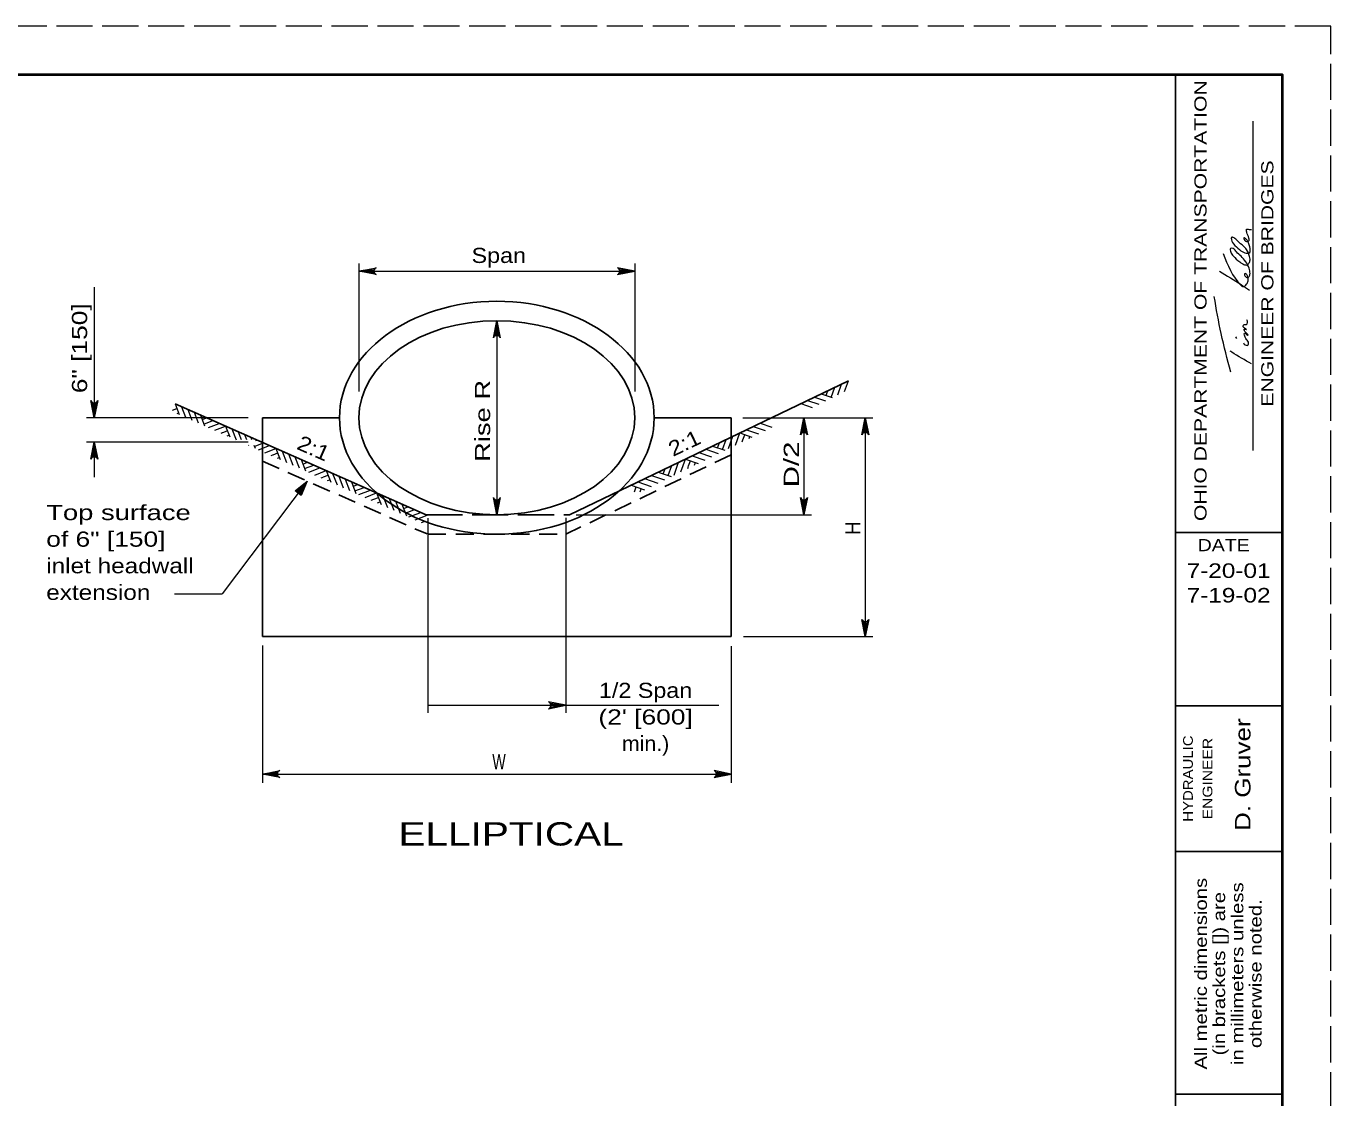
# Model space of a CAD drawing. Extents: x 685.4 to 719.4, y 1059.8 to 1105.8.
# Drawn here: x 706.01 to 719.44, y 1094.73 to 1105.77 of the extents above; entities that cross this region are included whole.
import ezdxf
from ezdxf.enums import TextEntityAlignment as Align

# ---------------------------------------------------------------- set-up
doc = ezdxf.new("R2010")
doc.units = 0
doc.header["$LTSCALE"] = 0.062
doc.linetypes.add('LONG_DASHED', pattern=[7.5, 6, -1.5])
doc.linetypes.add('MEDIUM_DASHED', pattern=[4.5, 3, -1.5])
doc.layers.add('1', color=7, linetype='Continuous', lineweight=13)

msp = doc.modelspace()

# ---------------------------------------------------------------- hatches: boundary and pattern name
at = {"layer": '1'}
msp.add_hatch(color=256, dxfattribs=at).paths.add_polyline_path([(708.78058, 1100.9845), (708.90567, 1101.08558), (708.84283, 1100.93758)])

# ---------------------------------------------------------------- linework, layer by layer
at = {"layer": '1', "lineweight": 25}
for p, q in [((687.44108, 1105.27067), (718.94108, 1105.27067)), ((717.84108, 1084.27067), (717.84108, 1105.27067)), ((718.94108, 1105.27067), (718.94108, 1084.27067)), ((714.47483, 1102.11825), (711.60375, 1100.738)), ((707.54717, 1101.88017), (710.13042, 1100.738)), ((708.4455, 1099.48433), (708.4455, 1101.73742)), ((708.4455, 1101.73742), (709.23825, 1101.73742)), ((712.47667, 1101.73742), (713.26933, 1101.73742)), ((713.26933, 1099.48433), (713.26933, 1101.73742)), ((718.94108, 1100.55483), (717.84108, 1100.55483)), ((708.4455, 1099.48433), (713.26933, 1099.48433)), ((718.94108, 1098.77067), (717.84108, 1098.77067)), ((718.94108, 1097.27067), (717.84108, 1097.27067)), ((718.94108, 1094.77067), (717.84108, 1094.77067))]:
    msp.add_line(p, q, dxfattribs=at)
at = {"layer": '1'}
for p, q in [((718.63983, 1101.40167), (718.63983, 1104.79175)), ((709.43817, 1103.32583), (709.43817, 1102.00808)), ((712.27683, 1103.32583), (712.27683, 1102.00808)), ((709.59842, 1103.26958), (709.43817, 1103.24717)), ((709.59292, 1103.2585), (709.43817, 1103.24717)), ((709.43817, 1103.24717), (712.27683, 1103.24717)), ((709.59133, 1103.24717), (709.43817, 1103.24717)), ((709.59417, 1103.23283), (709.43817, 1103.24717)), ((709.60025, 1103.22242), (709.43817, 1103.24717)), ((712.11467, 1103.22242), (712.27683, 1103.24717)), ((712.11658, 1103.26958), (712.27683, 1103.24717)), ((712.12083, 1103.23283), (712.27683, 1103.24717)), ((712.122, 1103.2585), (712.27683, 1103.24717)), ((712.12367, 1103.24717), (712.27683, 1103.24717)), ((706.71392, 1103.08342), (706.71392, 1101.73742)), ((710.83267, 1102.57467), (710.85742, 1102.73683)), ((710.84308, 1102.58083), (710.85742, 1102.73683)), ((710.85742, 1102.58367), (710.85742, 1102.73683)), ((710.86875, 1102.582), (710.85742, 1102.73683)), ((710.87983, 1102.57658), (710.85742, 1102.73683)), ((718.47233, 1102.55258), (718.46217, 1102.57183)), ((714.36567, 1101.97233), (714.40508, 1102.08467)), ((714.43575, 1102.00675), (714.47483, 1102.11825)), ((714.1255, 1101.95033), (714.2395, 1101.91042)), ((714.19542, 1101.98392), (714.30842, 1101.94425)), ((714.247, 1101.96575), (714.26517, 1102.0175)), ((714.29883, 1101.94758), (714.33517, 1102.05117)), ((706.6915, 1101.89767), (706.71392, 1101.73742)), ((706.70267, 1101.89225), (706.71392, 1101.73742)), ((706.73875, 1101.8995), (706.71392, 1101.73742)), ((706.72833, 1101.89342), (706.71392, 1101.73742)), ((706.71392, 1101.89058), (706.71392, 1101.73742)), ((707.5185, 1101.81542), (707.56525, 1101.83342)), ((707.54717, 1101.88017), (707.58917, 1101.77158)), ((707.61192, 1101.8515), (707.65408, 1101.74258)), ((707.67675, 1101.82292), (707.719, 1101.71358)), ((713.98567, 1101.88308), (714.10125, 1101.84258)), ((714.05558, 1101.91667), (714.17025, 1101.87642)), ((708.297, 1101.73742), (706.63525, 1101.73742)), ((707.56833, 1101.78083), (707.58333, 1101.78667)), ((707.74158, 1101.79417), (707.78408, 1101.6845)), ((707.80633, 1101.76558), (707.84892, 1101.6555)), ((707.82442, 1101.71892), (707.87108, 1101.73692)), ((707.8425, 1101.67208), (707.936, 1101.70825)), ((707.89042, 1101.63692), (708.00075, 1101.67958)), ((713.3895, 1101.73742), (714.72767, 1101.73742)), ((713.5665, 1101.68158), (713.68717, 1101.63925)), ((713.99258, 1101.57525), (714.01742, 1101.73742)), ((714.003, 1101.58142), (714.01742, 1101.73742)), ((714.01742, 1101.58425), (714.01742, 1101.73742)), ((714.02875, 1101.58258), (714.01742, 1101.73742)), ((714.03983, 1101.57717), (714.01742, 1101.73742)), ((714.62425, 1101.57525), (714.649, 1101.73742)), ((714.63458, 1101.58142), (714.649, 1101.73742)), ((714.649, 1101.58425), (714.649, 1101.73742)), ((714.66033, 1101.58258), (714.649, 1101.73742)), ((714.67142, 1101.57717), (714.649, 1101.73742)), ((707.95475, 1101.60817), (708.0655, 1101.65092)), ((708.01925, 1101.57942), (708.035, 1101.5855)), ((708.03692, 1101.58625), (708.0835, 1101.60433)), ((708.0655, 1101.65092), (708.10867, 1101.53933)), ((708.08367, 1101.55058), (708.10167, 1101.5575)), ((708.13025, 1101.62242), (708.17358, 1101.51033)), ((708.195, 1101.59375), (708.22633, 1101.51275)), ((708.25992, 1101.565), (708.28008, 1101.51275)), ((708.32467, 1101.53642), (708.33383, 1101.51275)), ((713.24283, 1101.42125), (713.28708, 1101.54717)), ((713.313, 1101.45575), (713.35683, 1101.58083)), ((713.35683, 1101.58083), (713.48, 1101.53767)), ((713.39042, 1101.51092), (713.40858, 1101.56267)), ((713.42667, 1101.61442), (713.54892, 1101.5715)), ((713.45342, 1101.52458), (713.46042, 1101.5445)), ((713.49658, 1101.64792), (713.618, 1101.60542)), ((708.297, 1101.4875), (706.63525, 1101.4875)), ((706.68917, 1101.32542), (706.71392, 1101.4875)), ((706.69958, 1101.33158), (706.71392, 1101.4875)), ((706.71392, 1101.4875), (706.71392, 1101.12642)), ((706.71392, 1101.33442), (706.71392, 1101.4875)), ((706.72525, 1101.33275), (706.71392, 1101.4875)), ((706.73633, 1101.32733), (706.71392, 1101.4875)), ((708.30242, 1101.45517), (708.3035, 1101.45233)), ((708.35608, 1101.45517), (708.3685, 1101.42333)), ((708.36083, 1101.44292), (708.45425, 1101.47908)), ((708.37475, 1101.50208), (708.38942, 1101.50775)), ((708.40567, 1101.40667), (708.51908, 1101.4505)), ((708.47008, 1101.37783), (708.58375, 1101.42183)), ((708.58375, 1101.42183), (708.62808, 1101.30725)), ((713.0075, 1101.41283), (713.13483, 1101.36817)), ((713.07742, 1101.44642), (713.20375, 1101.40208)), ((713.12908, 1101.42825), (713.14725, 1101.48)), ((713.18083, 1101.41008), (713.21717, 1101.51358)), ((713.38308, 1101.49008), (713.38967, 1101.50883)), ((708.5345, 1101.349), (708.55333, 1101.35633)), ((708.55517, 1101.357), (708.60183, 1101.37508)), ((708.599, 1101.32025), (708.61992, 1101.32833)), ((708.64858, 1101.39317), (708.69308, 1101.27817)), ((708.71333, 1101.3645), (708.75783, 1101.24917)), ((708.77817, 1101.33592), (708.823, 1101.22008)), ((708.84292, 1101.30725), (708.88783, 1101.19108)), ((708.861, 1101.2605), (708.90775, 1101.27858)), ((712.6815, 1101.14575), (712.72808, 1101.2785)), ((712.75167, 1101.18025), (712.79792, 1101.31208)), ((712.79792, 1101.31208), (712.92767, 1101.26658)), ((712.83142, 1101.24217), (712.84958, 1101.29392)), ((712.86767, 1101.34558), (712.99667, 1101.30042)), ((712.89208, 1101.24908), (712.90142, 1101.27575)), ((712.93758, 1101.37917), (713.06567, 1101.33433)), ((708.87917, 1101.21375), (708.97258, 1101.24992)), ((708.92108, 1101.17633), (709.03733, 1101.22125)), ((708.98542, 1101.1475), (709.10217, 1101.19267)), ((709.0735, 1101.12792), (709.12017, 1101.146)), ((709.10217, 1101.19267), (709.14758, 1101.075)), ((709.16683, 1101.164), (709.2125, 1101.04608)), ((709.23167, 1101.13542), (709.2775, 1101.017)), ((712.44858, 1101.14408), (712.5825, 1101.09708)), ((712.51842, 1101.17767), (712.65142, 1101.131)), ((712.57008, 1101.15958), (712.58825, 1101.21117)), ((712.62192, 1101.14142), (712.65817, 1101.24492)), ((712.82175, 1101.21458), (712.83067, 1101.24008)), ((708.90567, 1101.08558), (708.0305, 1099.92525)), ((709.04983, 1101.11875), (709.07167, 1101.12717)), ((709.11425, 1101.08992), (709.13825, 1101.09917)), ((709.2965, 1101.10667), (709.34242, 1100.988)), ((709.36125, 1101.078), (709.40733, 1100.95892)), ((709.37933, 1101.03142), (709.426, 1101.0495)), ((709.39742, 1100.98458), (709.49092, 1101.02075)), ((712.23892, 1101.04333), (712.37533, 1100.9955)), ((712.2725, 1100.9735), (712.29067, 1101.02517)), ((712.30867, 1101.07683), (712.44433, 1101.02933)), ((712.33067, 1100.97358), (712.34242, 1101.007)), ((712.37858, 1101.11042), (712.51333, 1101.06317)), ((709.43642, 1100.94592), (709.55567, 1100.99208)), ((709.50075, 1100.91717), (709.62042, 1100.9635)), ((709.56508, 1100.8885), (709.58992, 1100.89808)), ((709.59183, 1100.89875), (709.63842, 1100.91675)), ((709.62042, 1100.9635), (709.66708, 1100.84283)), ((709.62975, 1100.85958), (709.65658, 1100.87)), ((709.68517, 1100.93483), (709.732, 1100.81383)), ((709.74992, 1100.90625), (709.79692, 1100.78483)), ((709.81475, 1100.87758), (709.86192, 1100.75583)), ((710.835, 1100.89825), (710.85742, 1100.738)), ((710.84608, 1100.89275), (710.85742, 1100.738)), ((710.88225, 1100.90008), (710.85742, 1100.738)), ((710.87183, 1100.894), (710.85742, 1100.738)), ((710.85742, 1100.89117), (710.85742, 1100.738)), ((713.995, 1100.89825), (714.01742, 1100.738)), ((714.00608, 1100.89275), (714.01742, 1100.738)), ((714.04217, 1100.90008), (714.01742, 1100.738)), ((714.03175, 1100.894), (714.01742, 1100.738)), ((714.01742, 1100.89117), (714.01742, 1100.738)), ((709.87958, 1100.84892), (709.92683, 1100.72683)), ((709.89767, 1100.80217), (709.94433, 1100.82025)), ((709.91575, 1100.75542), (710.00917, 1100.7915)), ((709.95175, 1100.71567), (710.074, 1100.76292)), ((710.01608, 1100.68683), (710.13875, 1100.73433)), ((711.67375, 1100.738), (714.09608, 1100.738)), ((710.08042, 1100.65808), (710.10825, 1100.66883)), ((710.14783, 1100.70342), (710.14783, 1098.69767)), ((711.56717, 1100.708), (711.56717, 1098.69767)), ((707.54008, 1099.92525), (708.0305, 1099.92525)), ((714.62658, 1099.64458), (714.649, 1099.48433)), ((714.63767, 1099.63917), (714.649, 1099.48433)), ((714.67383, 1099.6465), (714.649, 1099.48433)), ((714.66342, 1099.64033), (714.649, 1099.48433)), ((714.649, 1099.6375), (714.649, 1099.48433)), ((708.4455, 1099.392), (708.4455, 1097.97833)), ((713.26933, 1099.38642), (713.26933, 1097.97833)), ((713.39508, 1099.48433), (714.72767, 1099.48433)), ((710.14783, 1098.77633), (713.14267, 1098.77633)), ((711.405, 1098.75158), (711.56717, 1098.77633)), ((711.40692, 1098.79875), (711.56717, 1098.77633)), ((711.41117, 1098.762), (711.56717, 1098.77633)), ((711.41233, 1098.78767), (711.56717, 1098.77633)), ((711.414, 1098.77633), (711.56717, 1098.77633)), ((708.60575, 1098.09075), (708.4455, 1098.06833)), ((708.60033, 1098.07967), (708.4455, 1098.06833)), ((708.59867, 1098.06833), (708.4455, 1098.06833)), ((708.6015, 1098.054), (708.4455, 1098.06833)), ((708.60767, 1098.04358), (708.4455, 1098.06833)), ((708.4455, 1098.06833), (713.26933, 1098.06833)), ((713.10717, 1098.04358), (713.26933, 1098.06833)), ((713.10908, 1098.09075), (713.26933, 1098.06833)), ((713.11333, 1098.054), (713.26933, 1098.06833)), ((713.1145, 1098.07967), (713.26933, 1098.06833)), ((713.11617, 1098.06833), (713.26933, 1098.06833))]:
    msp.add_line(p, q, dxfattribs=at)
at = {"layer": '1', "linetype": 'MEDIUM_DASHED', "lineweight": 25}
for p, q in [((708.4455, 1101.28908), (710.13875, 1100.54042)), ((713.26933, 1101.35633), (711.56725, 1100.53808)), ((710.14783, 1100.53808), (711.56725, 1100.53808))]:
    msp.add_line(p, q, dxfattribs=at)
at = {"layer": '1', "linetype": 'LONG_DASHED', "lineweight": 25}
msp.add_line((710.13042, 1100.738), (711.60375, 1100.738), dxfattribs=at)
at = {"layer": '1', "linetype": 'LONG_DASHED'}
msp.add_lwpolyline([(685.44108, 1083.77067), (719.44108, 1083.77067), (719.44108, 1105.77067), (685.44108, 1105.77067)], close=True, dxfattribs=at)
at = {"layer": '1', "lineweight": 40}
msp.add_lwpolyline([(687.44108, 1105.27067), (718.94108, 1105.27067), (718.94108, 1084.27067), (687.44108, 1084.27067)], close=True, dxfattribs=at)
at = {"layer": '1'}
for points in [[(709.61517, 1103.21183), (709.43817, 1103.24717), (709.61517, 1103.28258)], [(712.09983, 1103.21183), (712.27683, 1103.24717), (712.09983, 1103.28258)], [(710.822, 1102.55983), (710.85742, 1102.73683), (710.89283, 1102.55983)], [(710.8575, 1102.73683), (710.8575, 1101.61675), (710.8575, 1100.738)], [(706.74933, 1101.91442), (706.71392, 1101.73742), (706.67858, 1101.91442)], [(713.982, 1101.56042), (714.01742, 1101.73742), (714.05283, 1101.56042)], [(714.01742, 1101.73742), (714.01742, 1101.111), (714.01742, 1100.738)], [(714.61358, 1101.56042), (714.649, 1101.73742), (714.68442, 1101.56042)], [(714.649, 1101.73742), (714.649, 1100.372), (714.649, 1099.48433)], [(706.67858, 1101.3105), (706.71392, 1101.4875), (706.74933, 1101.3105)], [(710.89283, 1100.915), (710.85742, 1100.738), (710.822, 1100.915)], [(714.05283, 1100.915), (714.01742, 1100.738), (713.982, 1100.915)], [(714.68442, 1099.66133), (714.649, 1099.48433), (714.61358, 1099.66133)], [(711.39017, 1098.741), (711.56717, 1098.77633), (711.39017, 1098.81175)], [(708.6225, 1098.033), (708.4455, 1098.06833), (708.6225, 1098.10375)], [(713.09233, 1098.033), (713.26933, 1098.06833), (713.09233, 1098.10375)]]:
    msp.add_lwpolyline(points, dxfattribs=at)
msp.add_lwpolyline([(708.78058, 1100.9845), (708.90567, 1101.08558), (708.84283, 1100.93758)], close=True, dxfattribs=at)
for centre, start, end in [((709.62943, 1103.24723), 112.08782, 247.91395), ((712.08551, 1103.24723), 292.08605, 67.91218), ((710.85748, 1102.54553), 22.08782, 157.91395), ((706.71392, 1101.92869), 202.08782, 337.91395), ((714.01743, 1101.5461), 22.08782, 157.91395), ((714.64905, 1101.5461), 22.08782, 157.91395), ((706.71399, 1101.29624), 22.08782, 157.91395), ((710.8574, 1100.92926), 202.08782, 337.91395), ((714.01736, 1100.92926), 202.08782, 337.91395), ((714.64897, 1099.67566), 202.08782, 337.91395), ((711.37584, 1098.7764), 292.08605, 67.91218), ((708.63681, 1098.0684), 112.08782, 247.91395), ((713.07804, 1098.0684), 292.08605, 67.91218)]:
    msp.add_arc(centre, 0.0382, start, end, dxfattribs=at)
at = {"layer": '1', "lineweight": 25}
for major_axis, ratio in [((1.61924, 0), 0.740663), ((1.41933, 0), 0.704151)]:
    msp.add_ellipse((710.85744, 1101.7374), major_axis=major_axis, ratio=ratio, dxfattribs=at)
at = {"layer": '1'}
for points in [[(718.33292, 1103.42767), (718.51608, 1103.09933), (718.53125, 1103.08875), (718.54142, 1103.08875), (718.57333, 1103.11242), (718.58842, 1103.14658), (718.58342, 1103.19783), (718.5665, 1103.21967), (718.553, 1103.21967), (718.55125, 1103.20667), (718.56142, 1103.1915), (718.57492, 1103.18308), (718.59, 1103.18308), (718.60517, 1103.20467), (718.60858, 1103.224), (718.59833, 1103.27933), (718.51608, 1103.39975), (718.47058, 1103.44442), (718.43367, 1103.479), (718.4085, 1103.48117), (718.41025, 1103.44258), (718.43542, 1103.40383), (718.50267, 1103.3415), (718.54475, 1103.31608), (718.57842, 1103.31158), (718.60175, 1103.33758), (718.60858, 1103.37175), (718.6035, 1103.3975), (718.57333, 1103.47067), (718.54308, 1103.50267), (718.4825, 1103.55608), (718.45383, 1103.58192), (718.42033, 1103.59717), (718.41692, 1103.56917), (718.427, 1103.54333), (718.48417, 1103.48342), (718.55483, 1103.43617), (718.60683, 1103.4385), (718.60517, 1103.49617), (718.59333, 1103.53908), (718.58, 1103.56483), (718.56983, 1103.57558), (718.54642, 1103.59058), (718.54817, 1103.5735), (718.58342, 1103.552), (718.59833, 1103.56275), (718.58525, 1103.61642), (718.57667, 1103.64433), (718.57333, 1103.657), (718.57333, 1103.66983), (718.57333, 1103.6785), (718.59833, 1103.67633), (718.62375, 1103.67633)], [(718.29408, 1103.24542), (718.51783, 1103.10792), (718.6035, 1103.05225)], [(718.41033, 1102.20842), (718.31167, 1102.60367), (718.24042, 1102.986)], [(718.54142, 1102.50733), (718.54967, 1102.49667), (718.58683, 1102.48375), (718.59158, 1102.51617), (718.5665, 1102.55258), (718.55125, 1102.58883), (718.55125, 1102.60808), (718.5665, 1102.60183), (718.57667, 1102.591), (718.58683, 1102.58667), (718.56317, 1102.61883), (718.55125, 1102.63383), (718.54817, 1102.65117), (718.57158, 1102.64458), (718.56317, 1102.65325), (718.538, 1102.68108), (718.54817, 1102.69625), (718.56492, 1102.69825), (718.57333, 1102.69625), (718.58342, 1102.71758), (718.57667, 1102.7455)], [(718.6255, 1102.29283), (718.42033, 1102.41283), (718.40475, 1102.42325)]]:
    msp.add_spline(points, degree=3, dxfattribs=at)

# ---------------------------------------------------------------- texts
for s, height, width, p in [('OHIO DEPARTMENT OF TRANSPORTATION', 0.125, 1.3, (718.161, 1102.94292)), ('ENGINEER OF BRIDGES', 0.125, 1.3, (718.84933, 1103.11971)), ('D. Gruver', 0.16, 1.25, (718.6135, 1098.06217)), ('HYDRAULIC', 0.1, 1.15, (718.02017, 1098.02175)), ('ENGINEER', 0.1, 1.2, (718.22108, 1098.02179)), ('All metric dimensions', 0.125, 1.25, (718.16492, 1096.01275)), ('(in brackets []) are', 0.125, 1.25, (718.35242, 1096.01275)), ('in millimeters unless', 0.125, 1.25, (718.53992, 1096.01279)), ('otherwise noted.', 0.125, 1.25, (718.72742, 1096.01275))]:
    msp.add_text(s, height=height, rotation=90, dxfattribs=dict(at, width=width)).set_placement(p, align=Align.CENTER)
for s, height, width, p in [('Span', 0.156, 1.15, (710.59725, 1103.33125)), ('Top surface', 0.156, 1.35, (706.21992, 1100.68342)), ('of 6" [150]', 0.156, 1.3, (706.21992, 1100.40942)), ('inlet headwall', 0.156, 1.2, (706.21992, 1100.13542)), ('extension', 0.156, 1.2, (706.21992, 1099.86142)), ('W', 0.156, 0.7, (710.81083, 1098.11733)), ('ELLIPTICAL', 0.24, 1.3, (709.84458, 1097.33233))]:
    msp.add_text(s, height=height, dxfattribs=dict(at, width=width)).set_placement(p)
for s, rotation, width, p in [('6" [150]', 90, 1.3, (706.6405, 1101.99033)), ('Rise R', 90, 1.35, (710.78808, 1101.28258)), ('2:1', 336.147, 1.15, (708.78725, 1101.41942)), ('2:1', 25.676, 1.15, (712.67058, 1101.33367)), ('D/2', 90, 1.45, (713.96567, 1101.0215)), ('H', 90, 0.9, (714.59892, 1100.533))]:
    msp.add_text(s, height=0.156, rotation=rotation, dxfattribs=dict(at, width=width)).set_placement(p)
for s, height, width, p in [('DATE', 0.125, 1.2, (718.33779, 1100.36342)), ('7-20-01', 0.15, 1.25, (718.38812, 1100.08792)), ('7-19-02', 0.15, 1.25, (718.38812, 1099.83483)), ('1/2 Span', 0.156, 1.15, (712.38825, 1098.8525)), ("(2' [600]", 0.156, 1.3, (712.38825, 1098.5785)), ('min.)', 0.156, 1.05, (712.38829, 1098.3045))]:
    msp.add_text(s, height=height, dxfattribs=dict(at, width=width)).set_placement(p, align=Align.CENTER)

doc.saveas('drawing.dxf')
